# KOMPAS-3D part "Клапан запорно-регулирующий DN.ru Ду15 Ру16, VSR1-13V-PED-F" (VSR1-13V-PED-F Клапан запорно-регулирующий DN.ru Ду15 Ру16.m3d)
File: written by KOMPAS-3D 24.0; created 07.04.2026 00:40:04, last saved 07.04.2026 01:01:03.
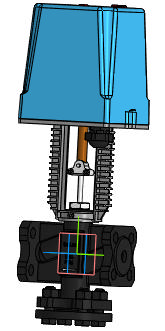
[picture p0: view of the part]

Document properties: Автор: R2D2; Полное имя файла: VSR1-13V-PED-F Клапан запорно-регулирующий DN.ru Ду15 Ру16.cdw

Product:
- Part/product: Клапан запорно-регулирующий DN.ru Ду15 Ру16  | designation VSR1-13V-PED-F
    Масса: 6.1
    Раздел спецификации: Прочие изделия
    Форматы листов документа: A3
    Примечание: D090-02882

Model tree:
1. Операция без истории:1  (labels: SHAPEOBJECT3D_ATTR_BUTT)

Expressions: VSR1-13V-PED-F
